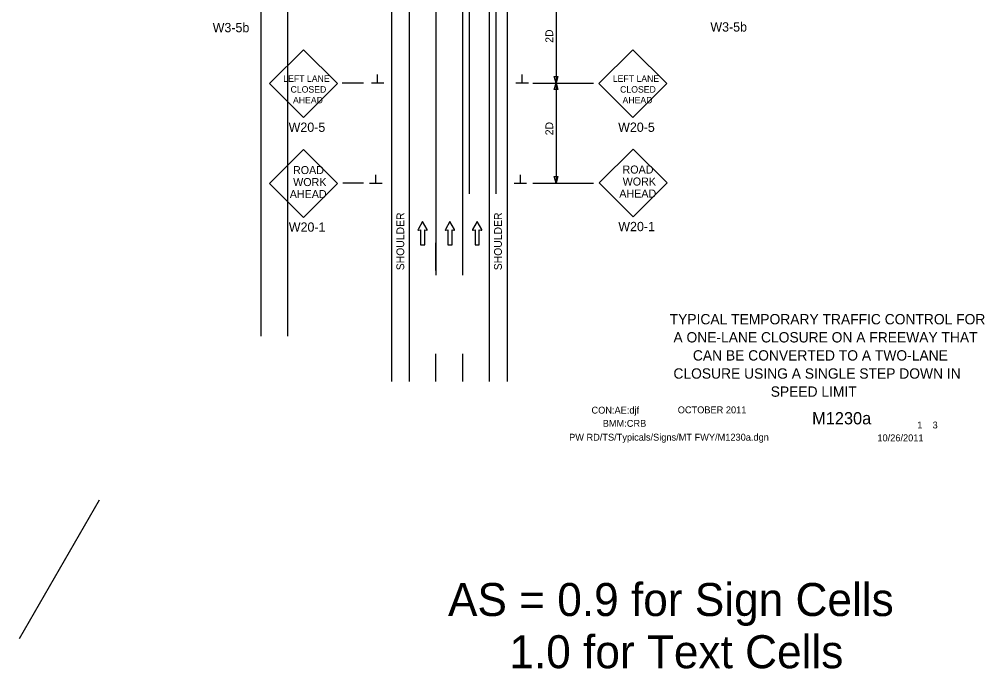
# Model space of a CAD drawing. Extents: x 16576 to 19508, y 5728 to 6974.
# Drawn here: x 16576 to 17444, y 5728 to 6313 of the extents above; entities that cross this region are included whole.
import ezdxf

# ---------------------------------------------------------------- set-up
doc = ezdxf.new("R2010")
doc.units = 0
for name, color, linetype in [('ALI_LEGAL_EX', 7, 'Continuous'), ('BORDER', 7, 'Continuous'), ('BORDER_SIGNAL_WO', 7, 'Continuous'), ('MT_SCRATCH_LEVEL_E', 7, 'Continuous'), ('PAVT_EDGE_EX', 7, 'Continuous'), ('TRAFFIC_SIGNS_PR', 7, 'Continuous'), ('TYPICAL_TEXT_DIMEN_PR', 7, 'Continuous')]:
    doc.layers.add(name, color=color, linetype=linetype)

msp = doc.modelspace()

# ---------------------------------------------------------------- linework, layer by layer
at = {"layer": 'ALI_LEGAL_EX'}
for p, q in [((16980.68, 6974.12), (16980.68, 6155.98)), ((17004.68, 6974.12), (17004.68, 6155.98)), ((16950.77, 6911.88), (16950.77, 6082.69)), ((16974.77, 6911.88), (16974.77, 6082.69)), ((16793.2, 6891.57), (16793.2, 6027.66)), ((16817.2, 6891.57), (16817.2, 6027.66))]:
    msp.add_line(p, q, dxfattribs=at)
for points in [[(16950.77, 6311.88), (16950.77, 6286.88)], [(16974.77, 6311.88), (16974.77, 6286.88)], [(16950.77, 6211.88), (16950.77, 6186.88)], [(16974.77, 6211.88), (16974.77, 6186.88)], [(16950.77, 6086.88), (16950.77, 6111.88)], [(16950.77, 6086.88), (16950.77, 6111.88)], [(16974.77, 6111.88), (16974.77, 6086.88)], [(16950.77, 5986.88), (16950.77, 6011.88)], [(16950.77, 5986.88), (16950.77, 6011.88)], [(16974.77, 6011.88), (16974.77, 5986.88)]]:
    msp.add_lwpolyline(points, dxfattribs=at)
at = {"layer": 'MT_SCRATCH_LEVEL_E'}
for p, q in [((16938.74, 6131.01), (16934.63, 6123.77)), ((16935.11, 6123.08), (16936.89, 6123.4)), ((16936.89, 6123.4), (16936.89, 6110.14)), ((16942.89, 6123.77), (16938.74, 6131.01)), ((16940.63, 6110.14), (16940.63, 6123.4)), ((16940.63, 6123.4), (16942.41, 6123.08)), ((16963.3, 6131.01), (16959.19, 6123.77)), ((16959.67, 6123.08), (16961.45, 6123.4)), ((16961.45, 6123.4), (16961.45, 6110.14)), ((16967.44, 6123.77), (16963.3, 6131.01)), ((16965.19, 6110.14), (16965.19, 6123.4)), ((16965.19, 6123.4), (16966.97, 6123.08)), ((16987.86, 6131.01), (16983.75, 6123.77)), ((16984.23, 6123.08), (16986.01, 6123.4)), ((16986.01, 6123.4), (16986.01, 6110.14)), ((16992, 6123.77), (16987.86, 6131.01)), ((16989.75, 6110.14), (16989.75, 6123.4)), ((16989.75, 6123.4), (16991.53, 6123.08)), ((16936.89, 6110.14), (16940.63, 6110.14)), ((16961.45, 6110.14), (16965.19, 6110.14)), ((16986.01, 6110.14), (16989.75, 6110.14))]:
    msp.add_line(p, q, dxfattribs=at)
for centre, start, end in [((16935.04, 6123.54), 150.42484, 279.96381), ((16942.48, 6123.54), 260.03619, 29.77312), ((16959.59, 6123.54), 150.42484, 279.96381), ((16967.04, 6123.54), 260.03619, 29.77312), ((16984.15, 6123.54), 150.42484, 279.96381), ((16991.59, 6123.54), 260.03619, 29.77312)]:
    msp.add_arc(centre, 0.463, start, end, dxfattribs=at)
at = {"layer": 'PAVT_EDGE_EX'}
for p, q in [((16910.77, 6923.28), (16910.77, 5986.88)), ((16926.77, 6923.28), (16926.77, 5986.88)), ((16998.77, 6923.28), (16998.77, 5986.88)), ((17014.77, 6923.28), (17014.77, 5986.88))]:
    msp.add_line(p, q, dxfattribs=at)
at = {"layer": 'TRAFFIC_SIGNS_PR'}
for p, q in [((16831.51, 6285.72), (16800.96, 6255.17)), ((16862.05, 6255.17), (16831.51, 6285.72)), ((17127.98, 6285.72), (17097.44, 6255.17)), ((17158.53, 6255.17), (17127.98, 6285.72)), ((16800.96, 6255.17), (16831.51, 6224.62)), ((16831.51, 6224.62), (16862.05, 6255.17)), ((17097.44, 6255.17), (17127.98, 6224.62)), ((17127.98, 6224.62), (17158.53, 6255.17)), ((16831.67, 6195.8), (16801.12, 6165.25)), ((16862.22, 6165.25), (16831.67, 6195.8)), ((17128.13, 6196.28), (17097.58, 6165.74)), ((17158.68, 6165.74), (17128.13, 6196.28)), ((16801.12, 6165.25), (16831.67, 6134.7)), ((16831.67, 6134.7), (16862.22, 6165.25)), ((17097.58, 6165.74), (17128.13, 6135.19)), ((17128.13, 6135.19), (17158.68, 6165.74))]:
    msp.add_line(p, q, dxfattribs=at)
at = {"layer": 'TYPICAL_TEXT_DIMEN_PR'}
for p, q in [((17058.77, 6345.62), (17058.77, 6255.62)), ((16898.24, 6255.57), (16898.24, 6263.35)), ((17028.29, 6255.57), (17028.29, 6263.35)), ((16885.71, 6255.62), (16866.35, 6255.62)), ((16903.87, 6255.57), (16892.62, 6255.57)), ((17033.92, 6255.57), (17022.67, 6255.57)), ((17037.77, 6255.62), (17092.5, 6255.62)), ((17058.77, 6255.62), (17057.2, 6261.48)), ((17057.2, 6261.48), (17058.77, 6261.48)), ((17057.2, 6249.76), (17058.77, 6255.62)), ((17058.77, 6261.48), (17060.34, 6261.48)), ((17060.34, 6261.48), (17058.77, 6255.62)), ((17058.77, 6255.62), (17058.77, 6165.62)), ((17058.77, 6255.62), (17060.34, 6249.76)), ((17058.77, 6249.76), (17057.2, 6249.76)), ((17060.34, 6249.76), (17058.77, 6249.76)), ((16896.65, 6165.12), (16896.65, 6172.9)), ((17026.7, 6165.12), (17026.7, 6172.9)), ((17058.77, 6165.62), (17057.2, 6171.48)), ((17057.2, 6171.48), (17058.77, 6171.48)), ((17058.77, 6171.48), (17060.34, 6171.48)), ((17060.34, 6171.48), (17058.77, 6165.62)), ((16885.71, 6165.62), (16866.86, 6165.62)), ((16902.28, 6165.12), (16891.03, 6165.12)), ((17032.33, 6165.12), (17021.08, 6165.12)), ((17037.77, 6165.62), (17092.5, 6165.62)), ((16647.75, 5880), (16575.89, 5755.4))]:
    msp.add_line(p, q, dxfattribs=at)

# ---------------------------------------------------------------- texts
at = {"layer": 'BORDER'}
for s, p in [('TYPICAL TEMPORARY TRAFFIC CONTROL FOR', (17161.04, 6038.42)), ('A ONE-LANE CLOSURE ON A FREEWAY THAT', (17164.42, 6022.12)), ('CAN BE CONVERTED TO A TWO-LANE ', (17181.92, 6005.82)), ('CLOSURE USING A SINGLE STEP DOWN IN ', (17164.42, 5989.52)), ('SPEED LIMIT', (17251.92, 5973.22))]:
    msp.add_text(s, height=9.3, dxfattribs=at).set_placement(p)
at = {"layer": 'BORDER_SIGNAL_WO'}
for s, height, p in [('CON:AE:djf  ', 6.2, (17090.69, 5958.06)), ('    OCTOBER 2011    ', 6.2, (17159.08, 5958.34)), ('    M1230a   ', 11, (17272.86, 5948.38)), ('BMM:CRB   ', 6.2, (17100.81, 5946.17)), (' 1    3 ', 6.2, (17381.45, 5944.7)), ('PW RD/TS/Typicals/Signs/MT FWY/M1230a.dgn      ', 6.2, (17070.55, 5933.71)), ('10/26/2011    ', 6.2, (17347.93, 5933.13)), ('AS = 0.9 for Sign Cells', 29.7271, (16961.58, 5775.8)), ('     1.0 for Text Cells', 29.7271, (16961.58, 5728.8))]:
    msp.add_text(s, height=height, dxfattribs=at).set_placement(p)
at = {"layer": 'TRAFFIC_SIGNS_PR'}
for s, height, p in [('W3-5b', 8.37, (16749.88, 6301.44)), ('W3-5b', 8.37, (17197.65, 6302.04)), ('LEFT LANE', 5.85, (16813.37, 6256.74)), ('LEFT LANE', 5.85, (17109.85, 6256.74)), ('CLOSED', 5.85, (16819.93, 6247.07)), ('CLOSED', 5.85, (17116.41, 6247.07)), ('AHEAD', 5.85, (16822.12, 6237.39)), ('AHEAD', 5.85, (17118.6, 6237.39)), ('W20-5', 8.37, (16818.2, 6211.75)), ('W20-5', 8.37, (17114.68, 6211.75)), ('ROAD', 7.2, (16822.16, 6173.73)), ('ROAD', 7.2, (17118.61, 6174.21)), ('WORK', 7.2, (16822.28, 6162.93)), ('WORK', 7.2, (17118.74, 6163.41)), ('AHEAD', 7.2, (16819.25, 6152.13)), ('AHEAD', 7.2, (17115.71, 6152.61)), ('W20-1', 8.37, (16818.36, 6121.83)), ('W20-1', 8.37, (17114.82, 6122.32))]:
    msp.add_text(s, height=height, dxfattribs=at).set_placement(p)
at = {"layer": 'TYPICAL_TEXT_DIMEN_PR'}
for s, p in [('2D', (17056.21, 6291.98)), ('2D', (17056.21, 6208.7)), ('SHOULDER', (16922.19, 6087.12)), ('SHOULDER', (17010.05, 6087.12))]:
    msp.add_text(s, height=7, rotation=90, dxfattribs=at).set_placement(p)

doc.saveas('drawing.dxf')
